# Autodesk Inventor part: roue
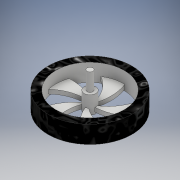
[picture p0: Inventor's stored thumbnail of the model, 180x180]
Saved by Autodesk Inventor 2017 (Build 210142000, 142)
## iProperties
Part Number: roue
Material: Générique
Document SubType Name: Modeling
Designer: Buhl
Density: 1 g/cm^3
Appearance: Par défaut
Author: Buhl
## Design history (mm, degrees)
sketch "Esquisse1"
  geometry: L1 (1.5, 0)-(3, 0); L2 (3, 0)-(3, -6); L3 (3, -9)-(0, -9); L4 (0, -9)-(0, 0); L5 (0, -9)-(3, -9); L6 (17.5, -6)-(3, -6); L7 (0, -6)-(0, -9); L8 (17.5, -9)-(21.5, -9); L9 (21.5, -9)-(21.5, 0); L10 (21.5, 0)-(17.5, 0); L11 (17.5, 0)-(17.5, -6); L12 (0, -9)-(1.5, -9); L13 (1.5, 0)-(1.5, 9.069); L14 (1.5, 9.069)-(0, 9.069); L15 (0, 9.069)-(0, -9); L16 (3, -9)-(3, -8.105); L17 (3, -8.105)-(17.5, -8.105); L18 (17.5, -8.105)-(17.5, -9)
  constraints: 36 end point, 8 parallel, 4 horizontal, 3 perpendicular, 1 point on line
  dimensions: "d0" = 9 distance between parallel lines of L1 L3; "d1" = 3 distance between parallel lines of L5 L6; "d2" = 4 distance between parallel lines of L9 L11; "d3" = 3 distance between parallel lines of L4 L2; "d10" = 21.5 distance between parallel lines of L9 L4
revolve "Révolution1" sketch "Esquisse1" stored, may be unused: angle "d4" = 90 deg
sketch "Esquisse2"
  geometry: A1 r 17.5 centre (0, 0) between (9.275, 14.84) and (16.511, 5.799) reference; A2 r 3 centre (0, 0) between (0, 3) and (2.164, 2.077) reference; A3 r 19.522 centre (18.819, -2.189) between (9.275, 14.84) and (0, 3); A4 r 24.81 centre (15.283, -18.98) between (16.511, 5.799) and (2.164, 2.077); A5 r 24.258 centre (-5.498, -4.401) between (16.511, 5.799) and (9.275, 14.84); A6 r 2.989 centre (0.008, 0.007) between (2.164, 2.077) and (2.164, 2.077); 1 further point
  constraints: 14 point on circle, 4 centre point, 1 tangent
extrude "Extrusion1" cut sketch "Esquisse2" distance "d5" = 10; taper "d6" = 0 deg
pattern_circular "Réseau circulaire1" dims angle "d8" = 360 deg
node "Solide1"
